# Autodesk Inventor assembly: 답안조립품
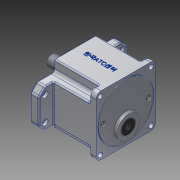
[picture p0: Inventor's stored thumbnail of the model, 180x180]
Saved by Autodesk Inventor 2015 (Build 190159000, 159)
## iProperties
Created: 2016-02
Part Number: 답안조립품
Document SubType Name: Assembly
Designer: Administrator
Author: Administrator
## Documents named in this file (10)
- C:\Users\Administrator\Desktop\460209V1009\답안조립품.iam
- C:\Users\Administrator\Desktop\460209V1009\본체.ipt
- C:\Users\Administrator\Desktop\460209V1009\커버.ipt
- C:\Users\Administrator\Desktop\460209V1009\오일실 8 22 7.ipt
- C:\Users\Administrator\Desktop\460209V1009\볼트 M4 x 10.ipt
- C:\Users\Administrator\Desktop\460209V1009\오일실 17 32 8.ipt
- C:\Users\Administrator\Desktop\460209V1009\베어링 608.ipt
- C:\Users\Administrator\Desktop\460209V1009\베어링 6003.ipt
- C:\Users\Administrator\Desktop\460209V1009\메인축.ipt
- C:\Users\Administrator\Desktop\460209V1009\서브축.ipt
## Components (2 placed, 1 different names)
1. ISO 4762 M4 x 10:1 — Insert:1
2. ISO 4762 M4 x 10:2 — Insert:2
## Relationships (2: Insert 2)
- Insert:1: ISO 4762 M4 x 10:1
- Insert:2: ISO 4762 M4 x 10:2
